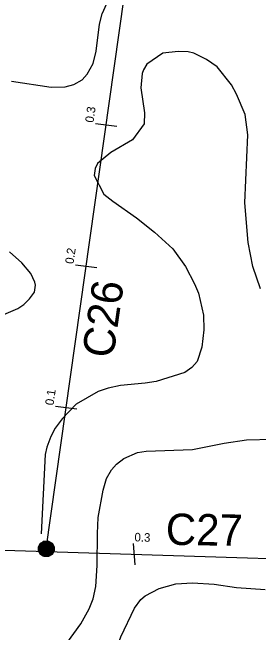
# Model space of a CAD drawing. Extents: x -645676 to -642474, y -1077513 to -1072613.
# Drawn here: x -643924.4 to -643751.8, y -1076481.9 to -1076047.4 of the extents above; entities that cross this region are included whole.
import ezdxf

# ---------------------------------------------------------------- set-up
doc = ezdxf.new("R2010")
doc.units = 0
for name, color, linetype in [('PC_NAVRH', 7, 'Continuous'), ('PC_POPIS_NAVRH', 7, 'Continuous'), ('PC_STAN_NAVRH', 7, 'Continuous'), ('VRSTEVNICE', 7, 'Continuous')]:
    doc.layers.add(name, color=color, linetype=linetype)

# ---------------------------------------------------------------- blocks, each defined once
blk = doc.blocks.new('$944')
blk.add_line((0, 1.5), (0, -1.5))
blk = doc.blocks.new('$406')
blk.add_lwpolyline([(-0.19, 0.72), (0.2, 0.72), (0.54, 0.53), (0.73, 0.19), (0.73, -0.2), (0.54, -0.54), (0.2, -0.73), (-0.19, -0.73), (-0.53, -0.54), (-0.72, -0.2), (-0.72, 0.19), (-0.53, 0.53), (-0.2, 0.72), (-0.28, 0.64), (0.28, 0.64), (0.44, 0.56), (-0.44, 0.56), (-0.52, 0.48), (0.52, 0.48), (0.56, 0.4), (-0.55, 0.4), (-0.6, 0.32), (0.6, 0.32), (0.68, 0.24), (-0.59, 0.24), (-0.65, 0.24), (-0.68, 0.16), (0.59, 0.16), (0.68, 0.16), (0.68, 0.08), (-0.59, 0.08), (-0.68, 0.08), (-0.68, 0), (0.59, 0), (0.68, 0), (0.68, -0.08), (-0.59, -0.08), (-0.68, -0.08), (-0.68, -0.16), (0.59, -0.16), (0.68, -0.16), (0.65, -0.24), (-0.62, -0.24), (-0.65, -0.24), (-0.6, -0.32), (0.6, -0.32), (0.56, -0.4), (-0.55, -0.4), (-0.52, -0.48), (0.52, -0.48), (0.44, -0.56), (-0.44, -0.56), (-0.28, -0.64), (0.28, -0.64), (-0.02, -0.69)])

msp = doc.modelspace()

# ---------------------------------------------------------------- linework, layer by layer
at = {"layer": 'PC_NAVRH'}
msp.add_line((-643900.68, -1076423.17), (-643836.19, -1075967.33), dxfattribs=at)
msp.add_lwpolyline([(-644139, -1076416.84), (-643996.94, -1076421.9), (-643507.65, -1076437.43), (-643217.45, -1076446.55)], dxfattribs=at)
at = {"layer": 'VRSTEVNICE'}
for points in [[(-643925.09, -1076095.65), (-643897.29, -1076099.7), (-643887.44, -1076099.41), (-643881.36, -1076097.96), (-643875.42, -1076094.63), (-643871.94, -1076090.58), (-643867.89, -1076083.19), (-643865.72, -1076074.5), (-643863.4, -1076055.68), (-643861.37, -1076048.43), (-643858.19, -1076041.19)], [(-643750.44, -1076241.05), (-643755.94, -1076225.41), (-643759.13, -1076208.46), (-643761.45, -1076180.8), (-643759.31, -1076133.12), (-643761.3, -1076118.82), (-643767.24, -1076104.63), (-643770.71, -1076098.11), (-643780.95, -1076085.5), (-643788.38, -1076080.29), (-643797.22, -1076075.95), (-643801.13, -1076075.08), (-643808.08, -1076074.79), (-643818.94, -1076075.95), (-643830.06, -1076083.55), (-643832.55, -1076087.54), (-643833.42, -1076090.14), (-643834.44, -1076100.28), (-643831.83, -1076117.66), (-643832.12, -1076125.33), (-643840.16, -1076136.54), (-643855.29, -1076145.46), (-643864.85, -1076153.28), (-643866.44, -1076156.76), (-643867.16, -1076161.54), (-643860.35, -1076174.77), (-643853.99, -1076179.64), (-643837.33, -1076191.37), (-643824.88, -1076201.37), (-643812.03, -1076213.1), (-643803.15, -1076225.41), (-643796.64, -1076237.57), (-643793.89, -1076244.09), (-643790.33, -1076259.51), (-643790.12, -1076269.72), (-643791.57, -1076281.89), (-643794.75, -1076292.02), (-643798.52, -1076296.22), (-643803.44, -1076299.55), (-643823.61, -1076305.93), (-643831.25, -1076307.23), (-643848.63, -1076308.68), (-643857.32, -1076310.56)], [(-643941.75, -1076263.64), (-643920.6, -1076254.8), (-643916.4, -1076252.05), (-643912.35, -1076248.14), (-643909.02, -1076243.36), (-643908.29, -1076238.44), (-643908.58, -1076236.27), (-643911.48, -1076230.33), (-643917.71, -1076222.8), (-643926.54, -1076215.12)], [(-643857.32, -1076310.56), (-643864.27, -1076312.88), (-643879.75, -1076321.94), (-643889.61, -1076332.14), (-643894.39, -1076338.66), (-643897.58, -1076344.45), (-643900.33, -1076351.98), (-643901.49, -1076357.19), (-643904.24, -1076412.66)], [(-643864.99, -1076434.82), (-643864.85, -1076412.51), (-643864.27, -1076401.22), (-643860.79, -1076382.1), (-643858.33, -1076373.99), (-643854.85, -1076367.91), (-643851.52, -1076363.86), (-643846.17, -1076359.8), (-643836.75, -1076355.6), (-643830.67, -1076354.73), (-643798.23, -1076353.57), (-643775.93, -1076349.23), (-643760.29, -1076346.91), (-643741.75, -1076346.33)], [(-643894.1, -1076500.28), (-643876.43, -1076475.66), (-643870.5, -1076465.23), (-643867.74, -1076458.28), (-643865.86, -1076449.59), (-643864.99, -1076434.82)], [(-643859.92, -1076510.7), (-643850.22, -1076489.85), (-643848.48, -1076484.78), (-643838.78, -1076464.65), (-643834.29, -1076458.71), (-643831.25, -1076456.11), (-643821.4, -1076450.89), (-643809.82, -1076447.71), (-643798.23, -1076446.98), (-643782.88, -1076448), (-643767.24, -1076450.17), (-643747.25, -1076451.76)]]:
    msp.add_lwpolyline(points, dxfattribs=at)

# ---------------------------------------------------------------- block references
at = {"layer": 'PC_STAN_NAVRH', "xscale": 5, "yscale": 4.999999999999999}
for p, rotation in [((-643858.66, -1076126.13), 83.38045299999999), ((-643872.67, -1076225.15), 83.38045299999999), ((-643886.67, -1076324.16), 83.38045299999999), ((-643839.17, -1076426.91), 4.436073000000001)]:
    msp.add_blockref('$944', p, dxfattribs=dict(at, rotation=rotation))
at = {"layer": 'PC_STAN_NAVRH', "xscale": 7.5, "yscale": 7.5}
msp.add_blockref('$406', (-643900.68, -1076423.17), dxfattribs=at)

# ---------------------------------------------------------------- texts
at = {"layer": 'PC_POPIS_NAVRH'}
for s, rotation, p in [('C26', 81.876, (-643853.82, -1076290.26)), ('C27', 359.073, (-643816.99, -1076420.34))]:
    msp.add_text(s, height=22, rotation=rotation, dxfattribs=at).set_placement(p)
at = {"layer": 'PC_STAN_NAVRH'}
for s, rotation, p in [('0.3', 81.933, (-643867.57, -1076124.88)), ('0.2', 81.933, (-643881.58, -1076223.89)), ('0.1', 81.933, (-643895.59, -1076322.91)), ('0.3', 358.213, (-643838.89, -1076417.92))]:
    msp.add_text(s, height=6, rotation=rotation, dxfattribs=at).set_placement(p)

doc.saveas('drawing.dxf')
